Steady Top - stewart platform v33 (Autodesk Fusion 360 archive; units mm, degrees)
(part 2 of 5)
sketch "Sketch19" plane through (-55, -80.325, 20.9) normal (-0.1726, 0.2017, 0.9641) x axis (-0.7598, -0.6502, 0)
  line L1 (-10.1354, 0) -> (10.0189, 0)
  circle C1 centre (0, 0) radius 5
  circle C2 centre (0, 0) radius 3
  circle C3 centre (0, 0) radius 1.5
  point P1 (0, 0)
  point P2 (0, 0)
  point P5 (0, 0)
  coincident P1 P2
  horizontal L1
  coincident P1 P5
  concentric C1 C3
  dimension "d114" diameter C1 = 10
  dimension "d115" diameter C2 = 6
  dimension "d188" diameter C3 = 3
sketch "Sketch23" plane through (0, -80.325, 0) normal (0, -1, 0) x axis (-1, 0, 0)
  circle C1 centre (55, -20.9) radius 8.75
extrude "Extrude22" add sketch "Sketch23" distance 14
copy_paste_bodies "CopyPasteBodies2"
move "Move2"
copy_paste_bodies "CopyPasteBodies3"
move "Move3"
move "Move4"
move "Move5"
revolve "Revolve4" sketch "Sketch19" AlongAngle 360
extrude "Extrude17" new body sketch "Sketch19" profile of L1 C2 along normal blind 20
extrude "Extrude18" new body sketch "Sketch19" profile of L1 C2 blind 10 taper 60 from offset 3
offset_faces "OffsetFaces1" distance -1
combine "Combine5"
sketch "Sketch20" plane through (0, 0, 120.9) normal (0, 0, 1) x axis (-1, 0, 0)
  circle C1 centre (72.8988, 59.4086) radius 2.5224
  circle C2 centre (72.8988, 59.4086) radius 1.625
  circle C3 centre (72.8988, 59.4086) radius 1.55
  concentric C1 C3
  dimension "d122" diameter C3 = 3.1
extrude "Extrude19" cut sketch "Sketch20" profile of C2 C3 against normal blind 6.037
sketch "Sketch21" plane through (0, 0, 123.9) normal (0, 0, 1) x axis (-1, 0, 0)
  circle C1 centre (72.8988, 59.4086) radius 4
  circle C2 centre (72.8988, 59.4086) radius 2.75
  circle C3 centre (72.8988, 59.4086) radius 2.75
extrude "Extrude20" cut sketch "Sketch21" profile of C2 C3 against normal blind 1.037
extrude "Extrude21" add sketch "Sketch13" against normal blind 1.15
offset_faces "OffsetFaces2" distance -0.05
extrude "Extrude23" new body sketch "Sketch10" profile of C1 L1 L2 L3 L8 L9 C2 C3 distance 8
sketch "Sketch24" plane through (0, 0, 124.9) normal (0, 0, 1) x axis (-1, 0, 0)
  line L1 (-64.9519, 82.5) -> (64.9519, 82.5)
  line L2 (-38.9711, -97.5) -> (-103.923, 15)
  line L3 (103.923, 15) -> (38.9711, -97.5)
  arc A1 centre (0, 0) radius 105 clockwise from (64.9519, 82.5) to (103.923, 15)
  arc A2 centre (0, 0) radius 105 clockwise from (-103.923, 15) to (-64.9519, 82.5)
  arc A3 centre (0, 0) radius 105 clockwise from (38.9711, -97.5) to (-38.9711, -97.5)
extrude "Extrude24" add sketch "Sketch19" profile of L1 C3 along normal blind 15
thread "Thread1" ThreadOffset 0 ThreadLength 10
hole "Hole1" HoleDepth 30 HoleDiameter 5.2 TipAngle 118 CBDepth 2 CBDiameter 9.5
circular_pattern "C-Pattern3" TotalAngle 360
canvas "Canvas1"
sketch "Sketch1" plane through (0, 0, 0) normal (1, 0, 0) x axis (0, 1, 0)
  line L1 (-4.2902, -11.5) -> (4.2902, -11.5)
  line L2 (-4.2902, 11.5) -> (-4.2902, -11.5)
  line L3 (4.2902, 11.5) -> (-4.2902, 11.5)
  line L4 (4.2902, -11.5) -> (4.2902, 11.5)
  line L5 (-4.2902, 11.5) -> (4.2902, -11.5)
  line L6 (4.2902, 11.5) -> (-4.2902, -11.5)
  line L7 (-2.75, -5.31) -> (-2.75, 0)
  line L8 (-4.2902, -5.31) -> (-2.75, -5.31)
  line L9 (0, -11.5) -> (0, 0)
  line L10 (-3.2902, -2.75) -> (-4.2902, -2.75)
  line L11 (-3.2902, 4.0144) -> (-3.2902, -2.75)
  line L12 (0, 11.5) -> (0, 0)
  line L13 (0, 7.0012) -> (-0.3033, 7.0012)
  circle C1 centre (0, 0) radius 1.5
  circle C2 centre (0, 0) radius 2.75
  arc A1 centre (-0.3033, 4.0144) radius 2.9868 clockwise from (-3.2902, 4.0144) to (-0.3033, 7.0012)
  point P6 (0, 0)
  point P1 (0, 0)
  point P7 (0, 0)
  point P9 (-2.75, 0)
  point P11 (-4.2902, -5.31)
  point P8 (0, 0)
  point P12 (0, 0)
  point P13 (0, -11.5)
  point P14 (-4.2902, -2.75)
  point P16 (0, 0)
  point P17 (0, 11.5)
  point P18 (0, 7.0012)
  point P2 (4.2902, -11.5)
  point P5 (4.2902, 11.5)
  horizontal L1
  perpendicular L1 L2
  parallel L1 L3
  parallel L2 L4
  coincident L5 P6
  coincident L6 P6
  coincident P1 P6
  coincident P6 P7
  concentric C1 C2
  coincident C2 P9
  tangent C2 L7
  vertical L7
  coincident L2 P11
  perpendicular L2 L8
  coincident P8 P12
  midpoint L1 P13
  coincident L2 P14
  perpendicular L2 L10
  perpendicular L10 L11
  tangent C2 L10
  coincident P8 P16
  midpoint L3 P17
  coincident L12 P18
  perpendicular L12 L13
  tangent L11 A1
  tangent L13 A1
  dimension "d1_1" distance P2 P5 = 23
  dimension "d2_1" diameter C1 = 3
  dimension "d3_1" diameter C2 = 5.5
  dimension "d4_1" distance L2 L11 = 1
  dimension "d5_1" radius A1 = 2.9868
revolve "Revolve1" sketch "Sketch1" AlongAngle 360 named "d6_1"
sketch "Sketch2" plane through (0, 0, 0) normal (1, 0, 0) x axis (0, 1, 0)
  line L1 (-3.2902, 4.0144) -> (-3.2902, -2.75)
  line L2 (0, 7.0012) -> (-0.3033, 7.0012)
  line L3 (0, 11.5) -> (0, 0)
  line L4 (0, 7.0012) -> (0.3033, 7.0012)
  line L5 (3.2902, 4.0144) -> (3.2902, -2.75)
  line L6 (3.2902, -2.75) -> (-3.2902, -2.75)
  arc A1 centre (-0.3033, 4.0144) radius 2.9868 clockwise from (-3.2902, 4.0144) to (-0.3033, 7.0012)
  arc A2 centre (0.3033, 4.0144) radius 2.9868 clockwise from (0.3033, 7.0012) to (3.2902, 4.0144)
  point P2 (-3.2902, -2.75)
  point P13 (3.2902, -2.75)
  point P3 (-3.2902, 4.0144)
  point P11 (3.2902, 4.0144)
  point P4 (-0.3033, 7.0012)
  point P10 (0.3033, 7.0012)
  point P6 (0, 7.0012)
  point P12 (0, 7.0012)
  point P14 (-3.2902, -2.75)
  symmetric P2 L3 P13
  symmetric P3 L3 P11
  symmetric P4 L3 P10
  symmetric A1 L3 A2
  symmetric P6 L3 P12
  coincident P2 P14
extrude "Extrude1" cut sketch "Sketch2" profile of L1 A1 L2 A2 L4 L5 L6 distance 8.05 named "d7_1"
sketch "Sketch3" plane through (0, 0, 0) normal (0, 1, 0) x axis (1, 0, 0)
  line L1 (-2.7532, 2.75) -> (-2.7532, -4.0144)
  line L2 (2.7532, 2.75) -> (-2.7532, 2.75)
  line L3 (2.7532, -4.0144) -> (2.7532, 2.75)
  line L4 (-2.7532, -4.0144) -> (2.7532, -4.0144)
  circle C1 centre (0, 0) radius 2.7532
  circle C2 centre (0, 0) radius 1.5
  point P1 (0, 0)
  point P6 (0, 0)
  point P7 (0, 0)
  coincident P1 P6
  tangent L1 C1
  coincident P1 P7
  dimension "d11_1" diameter C2 = 3
extrude "Extrude2" cut sketch "Sketch3" profile of L1 L2 L3 C1 C2 distance 6.947 named "d9_1"
sketch "Sketch4" plane through (0, 0, 11.5) normal (0, 0, 1) x axis (-1, 0, 0)
  circle C1 centre (0, 0) radius 4.2902
  circle C2 centre (0, 0) radius 2.5
  concentric C1 C2
  dimension "d12_1" diameter C2 = 5
extrude "Extrude3" cut sketch "Sketch4" profile of C2 against normal blind 7.2 named "d13_1"
sketch "Sketch5" plane through (0, 0, 0) normal (0, 1, 0) x axis (1, 0, 0)
  circle C1 centre (0, -9.2817) radius 1.25
  dimension "d15_1" diameter C1 = 2.5
extrude "Extrude4" cut sketch "Sketch5" along normal blind 9.938 named "d16_1"
fillet "Fillet1" radius 0.1 named "d19_1"
fillet "Fillet2" radius 0.1 named "d21_1"
component_from_bodies "Body->Comp1"
base_feature "Base Feature1"
position "Position1"
sketch "Sketch6" plane through (0, 0, 0) normal (1, 0, 0) x axis (0, 1, 0)
  line L1 (-3.25, -3.25) -> (3.25, -3.25)
  line L2 (-3.25, 3.25) -> (-3.25, -3.25)
  line L3 (3.25, 3.25) -> (-3.25, 3.25)
  line L4 (3.25, -3.25) -> (3.25, 3.25)
  line L5 (-3.25, 3.25) -> (3.25, -3.25)
  line L6 (3.25, 3.25) -> (-3.25, -3.25)
  circle C1 centre (0, 0) radius 1.5
  point P7 (0, 0)
  point P2 (0, 0)
  point P3 (3.25, -3.25)
  point P4 (-3.25, -3.25)
  horizontal L1
  perpendicular L1 L2
  parallel L1 L3
  parallel L2 L4
  coincident L5 P7
  coincident L6 P7
  coincident P2 P7
  equal L1 L4
  dimension "d22_1" distance P3 P4 = 6.5
extrude "Extrude5" new body sketch "Sketch6" profile of C1 L1 L2 L3 L4 distance -3.25 named "d23_1"
chamfer "Chamfer1" distance 0.55 named "d25_1"
extrude "Extrude6" add sketch "Sketch6" profile of C1 distance -5 named "d26_1"
sketch "Sketch7" plane through (0, 0, 0) normal (0, 1, 0) x axis (1, 0, 0)
  circle C1 centre (0, 0) radius 1.5
extrude "Extrude7" add sketch "Sketch7" distance 5 named "d28_1"
split "Split1"
split "Split2"
fillet "Fillet3" radius 0.2 named "d31_1"
chamfer "Chamfer1" distance 0.4 named "d34_1"
thread "Thread1" ThreadOffset 0 named "d36_1" ThreadLength 10 named "d37_1"
component_from_bodies "Body->Comp2"
joint "Assemble1" alignAngle 0 alignOffsetX 0 named "d41_1" alignOffsetY 0 named "d42_1" alignOffsetZ 0.04 named "d43_1"
joint "Assemble2" alignAngle -90 named "d44_1" alignOffsetX 0 named "d45_1" alignOffsetY 0 named "d46_1" alignOffsetZ 0.04 named "d47_1"
joint "Assemble3" alignAngle 0 alignOffsetX 0 alignOffsetY 0 alignOffsetZ 0
pipe "Pipe1" SectionSize 5 SectionThickness 1.25
offset_faces "OffsetFaces1" distance 4.152 (= "1.652 mm + 2.5 mm")
shell "Shell1" innerThickness 1
position "Position8"
joint "Assemble4" alignAngle -90 alignOffsetX 0 alignOffsetY 0 alignOffsetZ 0
offset_faces "OffsetFaces2" distance -2.5
offset_faces "OffsetFaces6" distance 1
offset_faces "OffsetFaces7" distance 1
combine "Combine7"
fillet "Fillet2" radius 0.75
fillet "Fillet3" radius 1
move "Move6"
base_feature "Base Feature1"
position "Position9"
position "Position10"
chamfer "Chamfer1" distance 0.4 named "d35_1_1"
thread "Thread2" ThreadOffset 0 named "d38_1_1" ThreadLength 10 named "d39_1_1"
base_feature "Base Feature1"
position "Position11"
position "Position12"
base_feature "Base Feature1"
position "Position13"
chamfer "Chamfer1" distance 0.4 named "d34_1_1"
thread "Thread1" ThreadOffset 0 named "d36_1_1" ThreadLength 10 named "d37_1_1"
position "Position14"
position "Position15"
joint "Assemble5" alignAngle 0 alignOffsetX 0 alignOffsetY 0 alignOffsetZ 0
joint "Assemble6" alignAngle 0 alignOffsetX 0 alignOffsetY 0 alignOffsetZ 0
joint "Assemble7" alignAngle 90 alignOffsetX 0 alignOffsetY 0 alignOffsetZ -0.04
joint "Assemble8" alignAngle 0 alignOffsetX 0 alignOffsetY 0 alignOffsetZ -0.04
position "Position16"
position "Position17"
position "Position18"
base_feature "Base Feature1"
joint "Assemble9" alignAngle 180 alignOffsetX 0 alignOffsetY 0 alignOffsetZ 0
component_from_bodies "Body->Comp1"
component_from_bodies "Body->Comp2"
mirror_component "MirrorComponent1"
derived_instance "DerivedInstance1"
derived_instance "DerivedInstance2"
derived_instance "DerivedInstance3"
derived_instance "DerivedInstance4"
derived_instance "DerivedInstance5"
derived_instance "DerivedInstance6"
derived_instance "DerivedInstance7"
step "00000000-0000-0000-0000-000000000000" TotalAngle 360
component_insert "Component Insert7"
position "Position19"
component_from_bodies "Body->Comp3"
component_from_bodies "Body->Comp4"
component_from_bodies "Body->Comp5"
work_plane "WorkPlane8" AlongDistance 20
sketch "Sketch25" plane through (0, 0, 57.7) normal (0, 0, 1) x axis (1, 0, 0)
  line L1 (-38.8652, 28.1835) -> (-43.8402, 19.5665)
  line L2 (-38.8869, 28.196) -> (-38.8652, 28.1835)
  line L3 (-28.8244, 45.6247) -> (-38.8869, 28.196)
  line L4 (-28.8027, 45.6122) -> (-28.8244, 45.6247)
  line L5 (-18.6803, 63.1448) -> (-28.8027, 45.6122)
  line L6 (28.8027, 45.6122) -> (18.6803, 63.1448)
  line L7 (28.8244, 45.6247) -> (28.8027, 45.6122)
  line L8 (38.8869, 28.196) -> (28.8244, 45.6247)
  line L9 (38.8652, 28.1835) -> (38.8869, 28.196)
  line L10 (43.8402, 19.5665) -> (38.8652, 28.1835)
  line L11 (43.8619, 19.579) -> (43.8402, 19.5665)
  line L12 (53.9244, 2.1503) -> (43.8619, 19.579)
  line L13 (53.9027, 2.1378) -> (53.9244, 2.1503)
  line L14 (64.0252, -15.3948) -> (53.9027, 2.1378)
  line L15 (25.1, -47.75) -> (45.3449, -47.75)
  line L16 (25.1, -47.775) -> (25.1, -47.75)
  line L17 (4.975, -47.775) -> (25.1, -47.775)
  line L18 (4.975, -47.75) -> (4.975, -47.775)
  line L19 (-4.975, -47.75) -> (4.975, -47.75)
  line L20 (-4.975, -47.775) -> (-4.975, -47.75)
  line L21 (-25.1, -47.775) -> (-4.975, -47.775)
  line L22 (-25.1, -47.75) -> (-25.1, -47.775)
  line L23 (-45.3449, -47.75) -> (-25.1, -47.75)
  line L24 (-53.9027, 2.1378) -> (-64.0252, -15.3948)
  line L25 (-53.9244, 2.1503) -> (-53.9027, 2.1378)
  line L26 (-43.8619, 19.579) -> (-53.9244, 2.1503)
  line L27 (-43.8402, 19.5665) -> (-43.8619, 19.579)
  line L28 (-78.9466, -12.9395) -> (-28.2673, 74.8395)
  line L29 (50.6793, -61.9) -> (-50.6793, -61.9)
  line L30 (28.2673, 74.8395) -> (78.9466, -12.9395)
  line L31 (-71.602, -14.2182) -> (-23.4876, 69.1182)
  line L32 (48.1143, -54.9) -> (-48.1143, -54.9)
  line L33 (23.4876, 69.1182) -> (71.602, -14.2182)
  line L34 (-63.1188, -15.5249) -> (-18.1144, 62.4249)
  line L35 (45.0043, -46.9) -> (-45.0043, -46.9)
  line L36 (18.1144, 62.4249) -> (63.1188, -15.5249)
  arc A1 centre (0, 0) radius 65.85 clockwise from (-18.6803, 63.1448) to (18.6803, 63.1448)
  arc A2 centre (0, 0) radius 65.85 clockwise from (64.0252, -15.3948) to (45.3449, -47.75)
  arc A3 centre (0, 0) radius 65.85 clockwise from (-45.3449, -47.75) to (-64.0252, -15.3948)
  arc A4 centre (0, 0) radius 80 clockwise from (-28.2673, 74.8395) to (28.2673, 74.8395)
  arc A5 centre (0, 0) radius 80 clockwise from (-50.6793, -61.9) to (-78.9466, -12.9395)
  arc A6 centre (0, 0) radius 80 clockwise from (78.9466, -12.9395) to (50.6793, -61.9)
  arc A7 centre (0, 0) radius 73 clockwise from (-23.4876, 69.1182) to (23.4876, 69.1182)
  arc A8 centre (0, 0) radius 73 clockwise from (-48.1143, -54.9) to (-71.602, -14.2182)
  arc A9 centre (0, 0) radius 73 clockwise from (71.602, -14.2182) to (48.1143, -54.9)
  arc A10 centre (0, 0) radius 65 clockwise from (-18.1144, 62.4249) to (18.1144, 62.4249)
  arc A11 centre (0, 0) radius 65 clockwise from (-45.0043, -46.9) to (-63.1188, -15.5249)
  arc A12 centre (0, 0) radius 65 clockwise from (63.1188, -15.5249) to (45.0043, -46.9)
  arc A13 centre (0, 0) radius 62 clockwise from (61.1836, -10.0282) to (39.2764, -47.9725)
  arc A14 centre (0, 0) radius 62 clockwise from (-21.9072, 58.0007) to (21.9072, 58.0007)
  arc A15 centre (0, 0) radius 62 clockwise from (-39.2764, -47.9725) to (-61.1836, -10.0282)
  dimension "d194" = -7
  dimension "d195" = -15
  dimension "d196" = -18
  dimension "d198" C-Pattern1-Angle = 360
extrude "Extrude25" new body sketch "Sketch25" profile of L31 A8 L32 A9 L33 A7 A12 L36 A10 L35 L34 A11 A13 A14 A15 along normal blind 3
extrude "Extrude26" add sketch "Sketch25" profile of A12 L36 A10 L35 L34 A11 A13 A14 A15 to an object
chamfer "Chamfer4" distance 8
component_insert "Component Insert8"
component_insert "Component Insert9"
component_insert "Component Insert10"
component_insert "Component Insert11"
combine "Combine1"
offset_faces "OffsetFaces1" distance 1.3
component_from_bodies "Body->Comp6"
component_insert "Component Insert12"
sketch "Sketch26" plane through (0, 0, 132.3423) normal (0, 0, -1) x axis (1, 0, 0)
  line L1 (-38.9711, -97.5) -> (-103.923, 15)
  line L2 (103.923, 15) -> (38.9711, -97.5)
  line L3 (-64.9519, 82.5) -> (64.9519, 82.5)
  line L4 (12.7, 8.89) -> (12.7, -8.89)
  line L5 (-10.16, 11.43) -> (10.16, 11.43)
  line L6 (-12.7, -8.89) -> (-12.7, 8.89)
  line L7 (10.16, -11.43) -> (-10.16, -11.43)
  line L8 (-10.16, 11.93) -> (10.16, 11.93)
  line L9 (-13.2, -8.89) -> (-13.2, 8.89)
  line L10 (10.16, -11.93) -> (-10.16, -11.93)
  line L11 (13.2, 8.89) -> (13.2, -8.89)
  line L12 (15.2, 8.89) -> (15.2, -8.89)
  line L13 (-10.16, 13.93) -> (10.16, 13.93)
  line L14 (-15.2, -8.89) -> (-15.2, 8.89)
  line L15 (10.16, -13.93) -> (-10.16, -13.93)
  circle C1 centre (15, -92.8365) radius 2.6
  circle C2 centre (-15, -92.8365) radius 2.6
  circle C3 centre (72.8988, 59.4086) radius 2.6
  circle C4 centre (87.8988, 33.4279) radius 2.6
  circle C5 centre (-87.8988, 33.4279) radius 2.6
  circle C6 centre (-72.8988, 59.4086) radius 2.6
  arc A1 centre (0, 0) radius 105 clockwise from (-103.923, 15) to (-64.9519, 82.5)
  arc A2 centre (0, 0) radius 105 clockwise from (38.9711, -97.5) to (-38.9711, -97.5)
  arc A3 centre (0, 0) radius 105 clockwise from (64.9519, 82.5) to (103.923, 15)
  circle C7 centre (10.16, 8.89) radius 1.25
  circle C8 centre (10.16, -8.89) radius 1.25
  circle C9 centre (-3.81, -8.89) radius 0.5
  circle C10 centre (1.27, -8.89) radius 0.5
  circle C11 centre (6.35, -8.89) radius 0.5
  circle C12 centre (-3.81, 8.89) radius 0.5
  circle C13 centre (1.27, 8.89) radius 0.5
  circle C14 centre (6.35, 8.89) radius 0.5
  circle C15 centre (-1.206, 6.223) radius 0.2415
  circle C16 centre (-1.143, 5.016) radius 0.2415
  circle C17 centre (0.894, 4) radius 0.2415
  circle C18 centre (11.684, 6.223) radius 0.2415
  circle C19 centre (3.921, 0.163) radius 0.197
  circle C20 centre (-9.252, 0.508) radius 0.2415
  circle C21 centre (-1.143, 1.778) radius 0.2415
  circle C22 centre (3.15, -2.501) radius 0.2415
  circle C23 centre (1.918, 2.286) radius 0.2415
  circle C24 centre (-9.186, -1.355) radius 0.2415
  circle C25 centre (9.449, 0.275) radius 0.2415
  circle C26 centre (5.08, -9.779) radius 0.2415
  circle C27 centre (8.064, -2.54) radius 0.2415
  circle C28 centre (10.096, -6.032) radius 0.2415
  circle C29 centre (-6.35, 6.731) radius 0.2415
  circle C30 centre (-11.43, 0.064) radius 0.2415
  circle C31 centre (-2.667, -5.144) radius 0.2415
  circle C32 centre (-3.238, -3.492) radius 0.2415
  circle C33 centre (-9.144, 1.968) radius 0.2415
  circle C34 centre (-8.064, -4.572) radius 0.2415
  circle C35 centre (9.398, 1.588) radius 0.2415
  circle C36 centre (6.668, 3.874) radius 0.2415
  circle C37 centre (-10.224, -4.572) radius 0.2415
  circle C38 centre (-9.258, -2.476) radius 0.2415
  circle C39 centre (9.309, -4) radius 0.2415
  circle C40 centre (0.444, 1.842) radius 0.197
  circle C41 centre (2.032, 4.382) radius 0.2415
  circle C42 centre (-1.143, 3.569) radius 0.2415
  circle C43 centre (1.397, 5.982) radius 0.2415
  circle C44 centre (-6.16, 2.54) radius 0.2415
  circle C45 centre (3.81, 8.89) radius 0.5
  circle C46 centre (-1.27, 8.89) radius 0.5
  circle C47 centre (-6.35, 8.89) radius 0.5
  circle C48 centre (3.81, -8.89) radius 0.5
  circle C49 centre (-1.27, -8.89) radius 0.5
  circle C50 centre (-6.35, -8.89) radius 0.5
  circle C51 centre (-10.16, -8.89) radius 1.25
  circle C52 centre (-10.16, 8.89) radius 1.25
  arc A4 centre (10.16, -8.89) radius 2.54 clockwise from (12.7, -8.89) to (10.16, -11.43)
  arc A5 centre (10.16, 8.89) radius 2.54 clockwise from (10.16, 11.43) to (12.7, 8.89)
  arc A6 centre (-10.16, 8.89) radius 2.54 clockwise from (-12.7, 8.89) to (-10.16, 11.43)
  arc A7 centre (-10.16, -8.89) radius 2.54 clockwise from (-10.16, -11.43) to (-12.7, -8.89)
  circle C53 centre (10.16, -8.89) radius 2.05
  circle C54 centre (-10.16, -8.89) radius 2.05
  circle C55 centre (-10.16, 8.89) radius 2.05
  circle C56 centre (10.16, 8.89) radius 2.05
  circle C57 centre (10.16, -8.89) radius 0.4
  circle C58 centre (-10.16, -8.89) radius 0.4
  circle C59 centre (-10.16, 8.89) radius 0.4
  circle C60 centre (10.16, 8.89) radius 0.4
  arc A8 centre (-10.16, 8.89) radius 3.04 clockwise from (-13.2, 8.89) to (-10.16, 11.93)
  arc A9 centre (-10.16, -8.89) radius 3.04 clockwise from (-10.16, -11.93) to (-13.2, -8.89)
  arc A10 centre (10.16, -8.89) radius 3.04 clockwise from (13.2, -8.89) to (10.16, -11.93)
  arc A11 centre (10.16, 8.89) radius 3.04 clockwise from (10.16, 11.93) to (13.2, 8.89)
  arc A12 centre (10.16, 8.89) radius 5.04 clockwise from (10.16, 13.93) to (15.2, 8.89)
  arc A13 centre (-10.16, 8.89) radius 5.04 clockwise from (-15.2, 8.89) to (-10.16, 13.93)
  arc A14 centre (-10.16, -8.89) radius 5.04 clockwise from (-10.16, -13.93) to (-15.2, -8.89)
  arc A15 centre (10.16, -8.89) radius 5.04 clockwise from (15.2, -8.89) to (10.16, -13.93)
  concentric C8 C57
  concentric C51 C58
  concentric C52 C59
  concentric C7 C60
  equal C57 C60
  equal C57 C58
  equal C58 C59
  dimension "d205" = 0.8
  dimension "d206" = 0.8
  dimension "d207" = 0.8
  dimension "d208" = 0.8
  dimension "d213" diameter C57 = 0.8
  dimension "d216" = 0.5
  dimension "d217" = 2.5
extrude "Extrude1" add sketch "Sketch26" profile of C7 C8 C51 C52 C53 C54 C55 C56 along normal blind 5
extrude "Extrude2" cut sketch "Sketch26" profile of C57 C58 C59 C60 along normal blind 8.776 and against normal blind 3
extrude "Extrude3" add sketch "Sketch26" profile of A11 A8 A10 A9 L11 L10 L9 L8 L12 A13 A12 A15 L13 A14 L15 L14 along normal blind 6.7
position "Position20"
sketch "Sketch27" plane through (0, 0, 140.3423) normal (0, 0, 1) x axis (-1, 0, 0)
  line L1 (-64.9519, 82.5) -> (64.9519, 82.5)
  line L2 (-38.9711, -97.5) -> (-103.923, 15)
  line L3 (103.923, 15) -> (38.9711, -97.5)
  circle C1 centre (-15, -92.8365) radius 4.75
  circle C2 centre (15, -92.8365) radius 4.75
  circle C3 centre (-72.8988, 59.4086) radius 4.75
  circle C4 centre (-87.8988, 33.4279) radius 4.75
  circle C5 centre (87.8988, 33.4279) radius 4.75
  circle C6 centre (72.8988, 59.4086) radius 4.75
  arc A1 centre (0, 0) radius 105 clockwise from (64.9519, 82.5) to (103.923, 15)
  arc A2 centre (0, 0) radius 105 clockwise from (-103.923, 15) to (-64.9519, 82.5)
  arc A3 centre (0, 0) radius 105 clockwise from (38.9711, -97.5) to (-38.9711, -97.5)
  circle C7 centre (11.1879, -4.7415) radius 1.48
  dimension "d220" diameter C7 = 2.96
extrude "Extrude4" cut sketch "Sketch27" profile of C7 against normal blind 12.262
chamfer "Chamfer1" distance 6.7
chamfer "Chamfer2" distance 1
pipe "Pipe1" SectionSize 5 named "d149_1" SectionThickness 1.25 named "d150_1"
offset_faces "OffsetFaces1" distance 4.152 (= "1.652 mm + 2.5 mm") named "d151_1"
shell "Shell1" innerThickness 1 named "d152_1"
offset_faces "OffsetFaces2" distance -2.5 named "d157_1"
offset_faces "OffsetFaces3" distance -29
component_insert "Component Insert13"
component_insert "Component Insert14"
component_insert "Component Insert15"
joint "Assemble10" alignAngle 180 alignOffsetX 0 alignOffsetY 0 alignOffsetZ 0
joint "Assemble11" alignAngle 180 alignOffsetX 0 alignOffsetY 0 alignOffsetZ 0
copy_paste "CopyPaste2"
copy_paste "CopyPaste3"
copy_paste "CopyPaste4"
copy_paste "CopyPaste5"
work_plane "WorkPlane9" AlongDistance -92.942
sketch "Sketch28" plane through (0, 0, 113.842) normal (0, 0, -1) x axis (-1, 0, 0)
  curve K1 (76.9182, -57.9086) -> (76.9593, -60.7935)
  line L1 (76.1889, -57.9086) -> (76.1889, -60.9086)
  line L2 (69.6086, -60.9086) -> (69.6086, -57.9086)
  curve K2 (68.8794, -57.9086) -> (68.8383, -60.7935)
  line L3 (69.6086, -59.4086) -> (76.1889, -59.4086)
  line L4 (72.7458, -55.9782) -> (72.8988, -59.4086)
  point P10 (76.1889, -59.4086)
  point P11 (69.6086, -59.4086)
  point P12 (72.8988, -59.4086)
  midpoint L1 P10
  midpoint L2 P11
  midpoint L3 P12
sketch "wire frame 2" plane through (0, 0, 20.9) normal (0, 0, -1) x axis (-1, 0, 0)
  line L1 (13.125, -83.925) -> (13.125, -87.325)
  line L2 (16.875, -87.325) -> (16.875, -83.925)
  line L3 (13.125, -81.45) -> (13.125, -83.925)
  line L4 (16.875, -83.925) -> (16.875, -81.45)
  curve K1 (14, -78.5) -> (13.1, -80)
  curve K2 (16.9, -80) -> (16, -78.5)
  line L5 (15, -80.325) -> (55, -80.325)
  line L6 (14, -78.5) -> (16, -78.5)
  line L7 (13.125, -87.325) -> (16.875, -87.325)
  line L8 (15, -78.5) -> (15, -87.325)
  line L9 (72.8988, -59.4086) -> (55, -80.325)
  line L10 (15, -80.325) -> (72.8988, -59.4086)
  line L11 (0, 20) -> (0, 2.5)
  line L12 (-15, -80.325) -> (-55, -80.325)
  circle C1 centre (55, -80.325) radius 5.075
  point P2 (55, -80.325)
  point P15 (55, -80.325)
  point P13 (16, -78.5)
  point P16 (16, -78.5)
  point P12 (14, -78.5)
  point P17 (14, -78.5)
  point P6 (16.875, -87.325)
  point P18 (16.875, -87.325)
  point P3 (13.125, -87.325)
  point P19 (13.125, -87.325)
  point P20 (15, -87.325)
  point P21 (15, -78.5)
  point P22 (15, -80.325)
  point P24 (55, -80.325)
  point P23 (72.8988, -59.4086)
  point P25 (72.8988, -59.4086)
  point P28 (-55, -80.325)
  point P29 (-15, -80.325)
  coincident P2 P15
  perpendicular L4 L5
  coincident P13 P16
  coincident P12 P17
  coincident P6 P18
  coincident P3 P19
  midpoint L7 P20
  midpoint L6 P21
  coincident L8 P22
  coincident P2 P24
  coincident P23 P25
  symmetric P15 L11 P28
  symmetric P22 L11 P29
  dimension "d235" distance P15 P22 = 40
  dimension "d236" distance P24 P25 = 96.9334
  dimension "d237" distance P22 P25 = 111.4808
sketch "Sketch30" plane through (0, 0, 20.9) normal (0, 0, -1) x axis (-1, 0, 0)
  line L1 (15, -80.325) -> (55, -80.325)
  circle C1 centre (0, 0) radius 81.7136
  point P1 (0, 0)
  point P4 (0, 0)
  point P3 (15, -80.325)
  coincident P1 P4
  coincident P3 C1
  dimension "d239" diameter C1 = 163.4271
sketch "Sketch31" plane through (0, 0, 113.842) normal (0, 0, -1) x axis (-1, 0, 0)
  line L1 (72.8988, -59.4086) -> (55, -80.325)
  line L2 (15, -80.325) -> (72.8988, -59.4086)
  line L3 (15, -80.325) -> (55, -80.325)
  circle C1 centre (0, 0) radius 94.0405
  point P1 (0, 0)
  point P6 (0, 0)
  point P3 (72.8988, -59.4086)
  coincident P1 P6
  coincident P3 C1
  dimension "d238" diameter C1 = 188.081
surface_patch "SurfacePatch1" sketch "wire frame 2"
mirror "Mirror1" mirrorStitchTolerance 0.1
sketch "Sketch32" plane through (0, 0, 20.9) normal (0, 0, -1) x axis (-1, 0, 0)
  line L1 (72.8988, -59.4086) -> (55, -80.325)
  line L2 (15, -80.325) -> (72.8988, -59.4086)
  line L3 (55, -80.325) -> (15, -80.325)
  line L4 (-55, -80.325) -> (-72.8988, -59.4086)
  line L5 (-15, -80.325) -> (-55, -80.325)
  line L6 (-72.8988, -59.4086) -> (-15, -80.325)
  line L7 (42.0635, 87.7939) -> (62.0635, 53.1529)
  line L8 (62.0635, 53.1529) -> (15, 92.8365)
  line L9 (15, 92.8365) -> (42.0635, 87.7939)
  line L10 (77.0635, 27.1721) -> (97.0635, -7.4689)
  line L11 (97.0635, -7.4689) -> (87.8988, -33.4279)
  line L12 (87.8988, -33.4279) -> (77.0635, 27.1721)
  line L13 (-97.0635, -7.4689) -> (-77.0635, 27.1721)
  line L14 (-77.0635, 27.1721) -> (-87.8988, -33.4279)
  line L15 (-87.8988, -33.4279) -> (-97.0635, -7.4689)
  line L16 (-62.0635, 53.1529) -> (-42.0635, 87.7939)
  line L17 (-42.0635, 87.7939) -> (-15, 92.8365)
  line L18 (-15, 92.8365) -> (-62.0635, 53.1529)
  point P4 (15, -80.325)
  point P7 (-15, -80.325)
  dimension "d260" distance P4 P7 = 30
  dimension "d243" C-Pattern1-Angle = 360
sketch "Sketch33" plane through (0, 0, 20.9) normal (0, 0, -1) x axis (-1, 0, 0)
  line L1 (55, -80.325) -> (15, -80.325)
  line L2 (-15, -80.325) -> (-55, -80.325)
  line L3 (-97.0635, -7.4689) -> (-77.0635, 27.1721)
  line L4 (-62.0635, 53.1529) -> (-42.0635, 87.7939)
  line L5 (42.0635, 87.7939) -> (62.0635, 53.1529)
  line L6 (77.0635, 27.1721) -> (97.0635, -7.4689)
  line L7 (-62.0635, 53.1529) -> (0, 0)
  line L8 (-77.0635, 27.1721) -> (0, 0)
  line L9 (-15, -80.325) -> (0, 0)
  line L10 (15, -80.325) -> (0, 0)
  line L11 (77.0635, 27.1721) -> (0, 0)
  line L12 (62.0635, 53.1529) -> (0, 0)
  line L13 (0, 20) -> (0, 2.5)
  curve K1
  curve K2
  curve K3
  curve K4
  curve K5
  curve K6
  curve K7
  curve K8
  line L14 (72.8988, -59.4086) -> (55, -80.325)
  line L15 (0, -80.325) -> (0, 0)
  line L16 (-15, -80.325) -> (15, -80.325)
  line L17 (-15, -45.6113) -> (-15, -80.325)
  line L18 (15, -46.194) -> (15, -80.325)
  circle C1 centre (0, 0) radius 81.7136
  point P1 (0, 0)
  point P14 (0, 0)
  point P15 (-62.0635, 53.1529)
  point P16 (0, 0)
  point P17 (-62.0635, 53.1529)
  point P18 (0, 0)
  point P6 (-77.0635, 27.1721)
  point P19 (-77.0635, 27.1721)
  point P20 (0, 0)
  point P5 (-15, -80.325)
  point P21 (-15, -80.325)
  point P22 (0, 0)
  point P2 (15, -80.325)
  point P23 (15, -80.325)
  point P24 (0, 0)
  point P13 (77.0635, 27.1721)
  point P25 (77.0635, 27.1721)
  point P26 (0, 0)
  point P10 (62.0635, 53.1529)
  point P27 (62.0635, 53.1529)
  point P32 (15, -80.325)
  point P33 (-15, -80.325)
  point P35 (15, -80.325)
  point P3 (55, -80.325)
  point P30 (72.8988, -59.4086)
  coincident P1 P14
  coincident C1 P15
  coincident P14 P16
  coincident P15 P17
  coincident P14 P18
  coincident P6 P19
  coincident P1 P20
  coincident P5 P21
  coincident P14 P22
  coincident P2 P23
  coincident P1 P24
  coincident P13 P25
  coincident P14 P26
  coincident P10 P27
  perpendicular L2 L15
  coincident P2 P32
  coincident P5 P33
  perpendicular L2 L17
  coincident P2 P35
  perpendicular L16 L18
  vertical L18
  vertical L17
  dimension "d249" angle L9 L10 = 21.155
  dimension "d252" distance P2 P3 = 40
  dimension "d253" angle L8 L10 = 120
  dimension "d259" distance P3 P30 = 96.9334
  dimension "d348" angle L10 L15 = 10.578
  dimension "d349" angle L9 L15 = 10.578
  dimension "d350" angle L8 L15 = 109.422
  dimension "d351" angle L7 L15 = 130.578
  dimension "d352" angle L12 L15 = 49.422
  dimension "d353" angle L11 L15 = 70.578
  dimension "d254" Text1-Height = 10
  dimension "d255" Text2-Height = 10
sketch "Sketch34" plane through (0, 0, 113.842) normal (0, 0, -1) x axis (-1, 0, 0)
  line L1 (0, 0) -> (72.8988, -59.4086)
  line L2 (-72.8988, -59.4086) -> (0, 0)
  circle C1 centre (0, 0) radius 94.0405
  point P1 (0, 0)
  point P8 (0, 0)
  point P2 (72.8988, -59.4086)
  point P9 (72.8988, -59.4086)
  point P10 (0, 0)
  point P3 (-72.8988, -59.4086)
  point P11 (-72.8988, -59.4086)
  coincident P1 P8
  coincident P2 C1
  coincident P2 P9
  coincident P1 P10
  coincident P3 P11
  dimension "d256" diameter C1 = 188.081
  dimension "d258" angle L1 L2 = 101.644
component_insert "Component Insert16"
component_insert "Component Insert17"
component_insert "Component Insert18"
work_plane "WorkPlane10" AlongDistance 0
position "Position21"
sketch "Sketch35" plane through (0, 0, 63.038) normal (0, 0, -1) x axis (-1, 0, 0)
  line L1 (34.0436, -12.6037) -> (11.6436, -12.6037)
  line L2 (10.0436, -11.0037) -> (10.0436, -7.2037)
  line L3 (11.6436, -5.6037) -> (31.0436, -5.6037)
  line L4 (34.0436, -2.6037) -> (34.0436, 16.3963)
  line L5 (31.0436, 19.3963) -> (13.6436, 19.3963)
  line L6 (12.0436, 20.9963) -> (12.0436, 34.3963)
  line L7 (9.0436, 37.3963) -> (-19.9564, 37.3963)
  line L8 (-22.9564, 34.3963) -> (-22.9564, -44.6037)
  line L9 (-19.9564, -47.6037) -> (34.0436, -47.6037)
  line L10 (37.0436, -44.6037) -> (37.0436, -15.6037)
  line L11 (-23.4876, 69.1182) -> (-71.602, -14.2182)
  line L12 (71.602, -14.2182) -> (23.4876, 69.1182)
  line L13 (-48.1143, -54.9) -> (48.1143, -54.9)
  line L14 (58.8354, -16.1059) -> (15.4696, 59.0059)
  line L15 (-43.3658, -42.9) -> (43.3658, -42.9)
  line L16 (-15.4696, 59.0059) -> (-58.8354, -16.1059)
  line L17 (-23.4876, 43) -> (23.4876, 43)
  line L18 (-23.4876, 103) -> (-23.4876, 43)
  line L19 (23.4876, 103) -> (-23.4876, 103)
  line L20 (23.4876, 43) -> (23.4876, 103)
  line L21 (-23.4876, 103) -> (23.4876, 43)
  line L22 (23.4876, 103) -> (-23.4876, 43)
  line L23 (-77.4568, -71.8409) -> (-25.4953, -41.8409)
  line L24 (-100.9444, -31.1591) -> (-77.4568, -71.8409)
  line L25 (-48.9829, -1.1591) -> (-100.9444, -31.1591)
  line L26 (-25.4953, -41.8409) -> (-48.9829, -1.1591)
  line L27 (100.9444, -31.1591) -> (48.9829, -1.1591)
  line L28 (77.4568, -71.8409) -> (100.9444, -31.1591)
  line L29 (25.4953, -41.8409) -> (77.4568, -71.8409)
  line L30 (48.9829, -1.1591) -> (25.4953, -41.8409)
  line L31 (-19.9564, -50.1037) -> (34.0436, -50.1037)
  line L32 (-25.4564, 34.3963) -> (-25.4564, -44.6037)
  line L33 (9.0436, 39.8963) -> (-19.9564, 39.8963)
  line L34 (14.5436, 21.8963) -> (14.5436, 34.3963)
  line L35 (31.0436, 21.8963) -> (14.5436, 21.8963)
  line L36 (36.5436, -2.6037) -> (36.5436, 16.3963)
  line L37 (12.5436, -8.1037) -> (31.0436, -8.1037)
  line L38 (12.5436, -10.1037) -> (12.5436, -8.1037)
  line L39 (34.0436, -10.1037) -> (12.5436, -10.1037)
  line L40 (39.5436, -44.6037) -> (39.5436, -15.6037)
  circle C1 centre (34.4286, -23.4298) radius 0.5334
  circle C2 centre (-14.9564, -5.1037) radius 0.45
  circle C3 centre (29.3486, -38.6698) radius 0.5334
  circle C4 centre (22.9186, 15.7713) radius 0.5
  circle C5 centre (21.7286, -23.4298) radius 0.5334
  circle C6 centre (28.9186, 13.2613) radius 0.52
  circle C7 centre (26.8086, -38.6698) radius 0.5334
  circle C8 centre (28.9186, 15.8013) radius 0.52
  circle C9 centre (29.3486, -23.4298) radius 0.5334
  circle C10 centre (28.9186, 5.6413) radius 0.52
  circle C11 centre (21.7286, -38.6698) radius 0.5334
  circle C12 centre (28.9186, 3.1013) radius 0.52
  circle C13 centre (24.2686, -23.4298) radius 0.5334
  circle C14 centre (28.9186, 8.1813) radius 0.52
  circle C15 centre (24.2686, -38.6698) radius 0.5334
  circle C16 centre (28.9186, 10.7213) radius 0.52
  circle C17 centre (31.8886, -23.4298) radius 0.5334
  circle C18 centre (31.9186, -43.2287) radius 0.45
  circle C19 centre (34.4286, -38.6698) radius 0.5334
  circle C20 centre (-17.4564, -22.1037) radius 0.45
  circle C21 centre (19.1886, -23.4298) radius 0.5334
  circle C22 centre (-0.4564, -15.1037) radius 0.45
  circle C23 centre (31.8886, -38.6698) radius 0.5334
  circle C24 centre (-14.4564, -38.7625) radius 0.45
  circle C25 centre (26.8086, -23.4298) radius 0.5334
  circle C26 centre (3.0872, 15.5174) radius 0.45
  circle C27 centre (28.9186, -1.9787) radius 0.52
  circle C28 centre (6.6686, -44.4171) radius 0.45
  circle C29 centre (19.1886, -38.6698) radius 0.5334
  circle C30 centre (28.9186, 0.5613) radius 0.52
  arc A1 centre (11.6436, -11.0037) radius 1.6 clockwise from (11.6436, -12.6037) to (10.0436, -11.0037)
  arc A2 centre (11.6436, -7.2037) radius 1.6 clockwise from (10.0436, -7.2037) to (11.6436, -5.6037)
  arc A3 centre (31.0436, -2.6037) radius 3 clockwise from (34.0436, -2.6037) to (31.0436, -5.6037)
  arc A4 centre (31.0436, 16.3963) radius 3 clockwise from (31.0436, 19.3963) to (34.0436, 16.3963)
  arc A5 centre (13.6436, 20.9963) radius 1.6 clockwise from (13.6436, 19.3963) to (12.0436, 20.9963)
  arc A6 centre (9.0436, 34.3963) radius 3 clockwise from (9.0436, 37.3963) to (12.0436, 34.3963)
  arc A7 centre (-19.9564, 34.3963) radius 3 clockwise from (-22.9564, 34.3963) to (-19.9564, 37.3963)
  arc A8 centre (-19.9564, -44.6037) radius 3 clockwise from (-19.9564, -47.6037) to (-22.9564, -44.6037)
  arc A9 centre (34.0436, -44.6037) radius 3 clockwise from (37.0436, -44.6037) to (34.0436, -47.6037)
  arc A10 centre (34.0436, -15.6037) radius 3 clockwise from (34.0436, -12.6037) to (37.0436, -15.6037)
  arc A11 centre (0, 0) radius 73 clockwise from (-23.4876, 69.1182) to (23.4876, 69.1182)
  arc A12 centre (0, 0) radius 73 clockwise from (71.602, -14.2182) to (48.1143, -54.9)
  arc A13 centre (0, 0) radius 73 clockwise from (-48.1143, -54.9) to (-71.602, -14.2182)
  arc A14 centre (0, 0) radius 61 clockwise from (60.8394, 4.423) to (26.5893, -54.9)
  arc A15 centre (0, 0) radius 61 clockwise from (-26.5893, -54.9) to (-60.8394, 4.423)
  arc A16 centre (0, 0) radius 61 clockwise from (-34.2502, 50.477) to (34.0436, 50.6165)
  arc A17 centre (-19.9564, -44.6037) radius 5.5 clockwise from (-19.9564, -50.1037) to (-25.4564, -44.6037)
  arc A18 centre (-19.9564, 34.3963) radius 5.5 clockwise from (-25.4564, 34.3963) to (-19.9564, 39.8963)
  arc A19 centre (9.0436, 34.3963) radius 5.5 clockwise from (9.0436, 39.8963) to (14.5436, 34.3963)
  arc A20 centre (31.0436, 16.3963) radius 5.5 clockwise from (31.0436, 21.8963) to (36.5436, 16.3963)
  arc A21 centre (31.0436, -2.6037) radius 5.5 clockwise from (36.5436, -2.6037) to (31.0436, -8.1037)
  arc A22 centre (34.0436, -15.6037) radius 5.5 clockwise from (34.0436, -10.1037) to (39.5436, -15.6037)
  arc A23 centre (34.0436, -44.6037) radius 5.5 clockwise from (39.5436, -44.6037) to (34.0436, -50.1037)
  point P72 (43.3658, -42.9)
  point P70 (58.8354, -16.1059)
  point P73 (-43.3658, -42.9)
  point P75 (-58.8354, -16.1059)
  point P76 (-15.4696, 59.0059)
  point P69 (15.4696, 59.0059)
  point P79 (-34.2502, 50.477)
  point P80 (-60.8394, 4.423)
  point P81 (-26.5893, -54.9)
  point P82 (26.5893, -54.9)
  point P83 (60.8394, 4.423)
  point P88 (0, 73)
  point P64 (23.4876, 69.1182)
  point P84 (23.4876, 43)
  point P87 (23.4876, 103)
  concentric A12 A14
  concentric A13 A15
  concentric A11 A16
  coincident P72 A14
  coincident P70 A14
  coincident P73 A15
  coincident P75 A15
  coincident P76 A16
  coincident P69 A16
  coincident L11 P79
  coincident L11 P80
  coincident L13 P81
  coincident L13 P82
  coincident L12 P83
  horizontal L17
  perpendicular L17 L18
  parallel L17 L19
  parallel L18 L20
  coincident L21 P88
  coincident L22 P88
  midpoint A11 P88
  coincident P64 L20
  dimension "d263" distance P84 P87 = 60
  dimension "d266" = 2.5
  dimension "d265" C-Pattern1-Angle = 360
extrude "Extrude27" new body sketch "Sketch35" profile of A16 A15 L15 L16 L14 A14 L18 L20 L23 L25 L27 L29 along normal blind 2.5
sketch "Sketch36" plane through (0, 0, 63.038) normal (0, 0, -1) x axis (-1, 0, 0)
  line L1 (-19.9564, -47.6037) -> (34.0436, -47.6037)
  line L2 (-22.9564, 34.3963) -> (-22.9564, -44.6037)
  line L3 (9.0436, 37.3963) -> (-19.9564, 37.3963)
  line L4 (12.0436, 20.9963) -> (12.0436, 34.3963)
  line L5 (31.0436, 19.3963) -> (13.6436, 19.3963)
  line L6 (34.0436, -2.6037) -> (34.0436, 16.3963)
  line L7 (11.6436, -5.6037) -> (31.0436, -5.6037)
  line L8 (10.0436, -11.0037) -> (10.0436, -7.2037)
  line L9 (34.0436, -12.6037) -> (11.6436, -12.6037)
  line L10 (37.0436, -44.6037) -> (37.0436, -15.6037)
  line L11 (-19.9564, -50.1037) -> (34.0436, -50.1037)
  line L12 (-25.4564, 34.3963) -> (-25.4564, -44.6037)
  line L13 (9.0436, 39.8963) -> (-19.9564, 39.8963)
  line L14 (14.5436, 21.8963) -> (14.5436, 34.3963)
  line L15 (31.0436, 21.8963) -> (14.5436, 21.8963)
  line L16 (36.5436, -2.6037) -> (36.5436, 16.3963)
  line L17 (12.5436, -8.1037) -> (31.0436, -8.1037)
  line L18 (12.5436, -10.1037) -> (12.5436, -8.1037)
  line L19 (34.0436, -10.1037) -> (12.5436, -10.1037)
  line L20 (39.5436, -44.6037) -> (39.5436, -15.6037)
  line L21 (36.0436, -44.6037) -> (36.0436, -15.6037)
  line L22 (34.0436, -13.6037) -> (11.6436, -13.6037)
  line L23 (9.0436, -11.0037) -> (9.0436, -7.2037)
  line L24 (11.6436, -4.6037) -> (31.0436, -4.6037)
  line L25 (33.0436, -2.6037) -> (33.0436, 16.3963)
  line L26 (31.0436, 18.3963) -> (13.6436, 18.3963)
  line L27 (11.0436, 20.9963) -> (11.0436, 34.3963)
  line L28 (9.0436, 36.3963) -> (-19.9564, 36.3963)
  line L29 (-21.9564, 34.3963) -> (-21.9564, -44.6037)
  line L30 (-19.9564, -46.6037) -> (34.0436, -46.6037)
  line L31 (38.9325, -44.6037) -> (38.9325, -15.6037)
  line L32 (-34.0436, -49.4926) -> (34.0436, -49.4926)
  line L33 (-24.8452, 34.3963) -> (-24.8452, -44.6037)
  line L34 (9.0436, 39.2852) -> (-19.9564, 39.2852)
  line L35 (13.9325, 21.2852) -> (13.9325, 34.3963)
  line L36 (31.0436, 21.2852) -> (13.9325, 21.2852)
  line L37 (35.9325, -2.6037) -> (35.9325, 16.3963)
  line L38 (11.9325, -7.4926) -> (31.0436, -7.4926)
  line L39 (11.9325, -10.7148) -> (11.9325, -7.4926)
  line L40 (34.0436, -10.7148) -> (11.9325, -10.7148)
  line L41 (0, -75.7937) -> (0, 0)
  line L42 (-24.8452, -36.3956) -> (-38.9325, -44.6037)
  line L43 (-28.0468, -44.6037) -> (-19.9564, -44.6037)
  line L44 (-28.0468, -52.4264) -> (-28.0468, -44.6037)
  line L45 (-19.9564, -52.4264) -> (-28.0468, -52.4264)
  line L46 (-19.9564, -44.6037) -> (-19.9564, -52.4264)
  line L47 (42.0931, -44.6037) -> (34.0436, -44.6037)
  line L48 (42.0931, -52.7689) -> (42.0931, -44.6037)
  line L49 (34.0436, -52.7689) -> (42.0931, -52.7689)
  line L50 (34.0436, -44.6037) -> (34.0436, -52.7689)
  line L51 (42.0931, -15.6037) -> (34.0436, -15.6037)
  line L52 (42.0931, -9.0313) -> (42.0931, -15.6037)
  line L53 (34.0436, -9.0313) -> (42.0931, -9.0313)
  line L54 (34.0436, -15.6037) -> (34.0436, -9.0313)
  line L55 (38.0684, -2.6037) -> (31.0436, -2.6037)
  line L56 (38.0684, -9.0313) -> (38.0684, -2.6037)
  line L57 (31.0436, -9.0313) -> (38.0684, -9.0313)
  line L58 (31.0436, -2.6037) -> (31.0436, -9.0313)
  line L59 (38.0684, 16.3963) -> (31.0436, 16.3963)
  line L60 (38.0684, 23.4431) -> (38.0684, 16.3963)
  line L61 (31.0436, 23.4431) -> (38.0684, 23.4431)
  line L62 (31.0436, 16.3963) -> (31.0436, 23.4431)
  line L63 (16.4916, 34.3963) -> (9.0436, 34.3963)
  line L64 (16.4916, 41.6027) -> (16.4916, 34.3963)
  line L65 (9.0436, 41.6027) -> (16.4916, 41.6027)
  line L66 (9.0436, 34.3963) -> (9.0436, 41.6027)
  line L67 (-26.0166, 34.3963) -> (-19.9564, 34.3963)
  line L68 (-26.0166, 40.5491) -> (-26.0166, 34.3963)
  line L69 (-19.9564, 40.5491) -> (-26.0166, 40.5491)
  line L70 (-19.9564, 34.3963) -> (-19.9564, 40.5491)
  arc A1 centre (34.0436, -44.6037) radius 3 clockwise from (37.0436, -44.6037) to (34.0436, -47.6037)
  arc A2 centre (-19.9564, -44.6037) radius 3 clockwise from (-19.9564, -47.6037) to (-22.9564, -44.6037)
  arc A3 centre (-19.9564, 34.3963) radius 3 clockwise from (-22.9564, 34.3963) to (-19.9564, 37.3963)
  arc A4 centre (9.0436, 34.3963) radius 3 clockwise from (9.0436, 37.3963) to (12.0436, 34.3963)
  arc A5 centre (13.6436, 20.9963) radius 1.6 clockwise from (13.6436, 19.3963) to (12.0436, 20.9963)
  arc A6 centre (31.0436, 16.3963) radius 3 clockwise from (31.0436, 19.3963) to (34.0436, 16.3963)
  arc A7 centre (31.0436, -2.6037) radius 3 clockwise from (34.0436, -2.6037) to (31.0436, -5.6037)
  arc A8 centre (11.6436, -7.2037) radius 1.6 clockwise from (10.0436, -7.2037) to (11.6436, -5.6037)
  arc A9 centre (11.6436, -11.0037) radius 1.6 clockwise from (11.6436, -12.6037) to (10.0436, -11.0037)
  arc A10 centre (34.0436, -15.6037) radius 3 clockwise from (34.0436, -12.6037) to (37.0436, -15.6037)
  arc A11 centre (34.0436, -44.6037) radius 5.5 clockwise from (39.5436, -44.6037) to (34.0436, -50.1037)
  arc A12 centre (-19.9564, -44.6037) radius 5.5 clockwise from (-19.9564, -50.1037) to (-25.4564, -44.6037)
  arc A13 centre (-19.9564, 34.3963) radius 5.5 clockwise from (-25.4564, 34.3963) to (-19.9564, 39.8963)
  arc A14 centre (9.0436, 34.3963) radius 5.5 clockwise from (9.0436, 39.8963) to (14.5436, 34.3963)
  arc A15 centre (31.0436, 16.3963) radius 5.5 clockwise from (31.0436, 21.8963) to (36.5436, 16.3963)
  arc A16 centre (31.0436, -2.6037) radius 5.5 clockwise from (36.5436, -2.6037) to (31.0436, -8.1037)
  arc A17 centre (34.0436, -15.6037) radius 5.5 clockwise from (34.0436, -10.1037) to (39.5436, -15.6037)
  arc A18 centre (34.0436, -44.6037) radius 2 clockwise from (36.0436, -44.6037) to (34.0436, -46.6037)
  arc A19 centre (34.0436, -15.6037) radius 2 clockwise from (34.0436, -13.6037) to (36.0436, -15.6037)
  arc A20 centre (11.6436, -11.0037) radius 2.6 clockwise from (11.6436, -13.6037) to (9.0436, -11.0037)
  arc A21 centre (11.6436, -7.2037) radius 2.6 clockwise from (9.0436, -7.2037) to (11.6436, -4.6037)
  arc A22 centre (31.0436, -2.6037) radius 2 clockwise from (33.0436, -2.6037) to (31.0436, -4.6037)
  arc A23 centre (31.0436, 16.3963) radius 2 clockwise from (31.0436, 18.3963) to (33.0436, 16.3963)
  arc A24 centre (13.6436, 20.9963) radius 2.6 clockwise from (13.6436, 18.3963) to (11.0436, 20.9963)
  arc A25 centre (9.0436, 34.3963) radius 2 clockwise from (9.0436, 36.3963) to (11.0436, 34.3963)
  arc A26 centre (-19.9564, 34.3963) radius 2 clockwise from (-21.9564, 34.3963) to (-19.9564, 36.3963)
  arc A27 centre (-19.9564, -44.6037) radius 2 clockwise from (-19.9564, -46.6037) to (-21.9564, -44.6037)
  arc A28 centre (34.0436, -44.6037) radius 4.8889 clockwise from (38.9325, -44.6037) to (34.0436, -49.4926)
  arc A29 centre (-19.9564, -44.6037) radius 4.8889 clockwise from (-19.9564, -49.4926) to (-24.8452, -44.6037)
  arc A30 centre (-19.9564, 34.3963) radius 4.8889 clockwise from (-24.8452, 34.3963) to (-19.9564, 39.2852)
  arc A31 centre (9.0436, 34.3963) radius 4.8889 clockwise from (9.0436, 39.2852) to (13.9325, 34.3963)
  arc A32 centre (31.0436, 16.3963) radius 4.8889 clockwise from (31.0436, 21.2852) to (35.9325, 16.3963)
  arc A33 centre (31.0436, -2.6037) radius 4.8889 clockwise from (35.9325, -2.6037) to (31.0436, -7.4926)
  arc A34 centre (34.0436, -15.6037) radius 4.8889 clockwise from (34.0436, -10.7148) to (38.9325, -15.6037)
  arc A35 centre (-34.0436, -44.6037) radius 4.8889 clockwise from (-34.0436, -49.4926) to (-38.9325, -44.6037)
  point P1 (0, 0)
  point P110 (0, 0)
  point P87 (38.9325, -44.6037)
  point P114 (-38.9325, -44.6037)
  point P89 (34.0436, -49.4926)
  point P113 (-34.0436, -49.4926)
  point P90 (-19.9564, -49.4926)
  point P115 (-24.8452, -36.3956)
  point P91 (-19.9564, -44.6037)
  point P116 (-19.9564, -44.6037)
  point P88 (34.0436, -44.6037)
  point P120 (34.0436, -44.6037)
  point P31 (34.0436, -15.6037)
  point P124 (34.0436, -15.6037)
  point P130 (38.0684, -9.0313)
  point P104 (31.0436, -2.6037)
  point P128 (31.0436, -2.6037)
  point P101 (31.0436, 16.3963)
  point P132 (31.0436, 16.3963)
  point P43 (9.0436, 34.3963)
  point P136 (9.0436, 34.3963)
  point P40 (-19.9564, 34.3963)
  point P140 (-19.9564, 34.3963)
  coincident P1 P110
  parallel L29 L41
  symmetric P87 L41 P114
  symmetric P89 L41 P113
  symmetric A28 L41 A35
  concentric A1 A28
  concentric A2 A29
  concentric A3 A30
  concentric A4 A31
  concentric A6 A32
  concentric A7 A33
  concentric A10 A34
  tangent L40 A34
  tangent A33 L38
  tangent A32 L37
  tangent L36 A32
  tangent L37 A33
  tangent L34 A31
  tangent A30 L34
  tangent A28 L32
  tangent A29 L33
  tangent A31 L35
  tangent L33 A30
  tangent L32 A29
  tangent L31 A28
  tangent L31 A34
  coincident P90 L32
  coincident L33 P115
  horizontal L43
  vertical L44
  horizontal L45
  vertical L46
  coincident P91 P116
  horizontal L47
  vertical L48
  horizontal L49
  vertical L50
  coincident P88 P120
  horizontal L51
  vertical L52
  horizontal L53
  vertical L54
  coincident P31 P124
  horizontal L55
  vertical L56
  horizontal L57
  vertical L58
  midpoint L53 P130
  coincident P104 P128
  horizontal L59
  vertical L60
  horizontal L61
  vertical L62
  coincident P101 P132
  horizontal L63
  vertical L64
  horizontal L65
  vertical L66
  coincident P43 P136
  horizontal L67
  vertical L68
  horizontal L69
  vertical L70
  coincident P40 P140
  dimension "d269" = 1
extrude "Extrude28" add sketch "Sketch36" profile of A1 L1 A2 L2 A3 L3 A4 L4 A5 L5 A6 L6 A7 L7 A8 L8 A9 L9 A10 L10 A12 L12 A18 A20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 along normal blind 2.5
extrude "Extrude29" cut sketch "Sketch36" profile of A18 A20 L25 A26 L27 A21 A19 A27 L24 A23 L28 L21 L29 L30 A22 L22 A25 A24 L23 L26 to an object
extrude "Extrude30" add sketch "Sketch36" profile of A1 A2 A3 A4 A6 A7 A10 A11 A12 A13 A14 A15 A16 A17 A28 A29 A34 A33 A32 A31 L32 A30 L43 L46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 against normal blind 2.5
loft "Loft1"
loft "Loft2"
loft "Loft3"
step "SurfaceOffset1" offset 0
step "SurfaceOffset2" offset 0
step "SurfaceOffset3" offset 0
surface_delete_face "SurfaceDeleteFace1"
surface_stitch "SurfaceStitch1" StitchingTolerence 0.1
thicken "Thicken1" Thickness -3
surface_stitch "SurfaceStitch2" StitchingTolerence 0.1
thicken "Thicken2" Thickness -3
surface_stitch "SurfaceStitch3" StitchingTolerence 0.1
thicken "Thicken3" Thickness -3
combine "Combine8"
fillet "Fillet4" radius 2
fillet "Fillet5" radius 3.016
fillet "Fillet6" radius 68.204
fillet "Fillet7" radius 405.4855
fillet "Fillet8" radius 8
pipe "Pipe1" SectionSize 1 SectionThickness 0.25
fillet "Fillet9" radius 1.1
pipe "Pipe2" SectionSize 1 SectionThickness 0.25
pipe "Pipe3" SectionSize 1 SectionThickness 0.25
pipe "Pipe4" SectionSize 1 SectionThickness 0.25
pipe "Pipe5" SectionSize 1 SectionThickness 0.25
sketch "Sketch37" plane through (0, 0, 0) normal (0, 1, 0) x axis (1, 0, 0)
  line L1 (7.5, -53.5) -> (-7.5, -53.5)
  line L2 (7.5, -46.5) -> (7.5, -53.5)
  line L3 (-7.5, -46.5) -> (7.5, -46.5)
  line L4 (-7.5, -53.5) -> (-7.5, -46.5)
  line L5 (7.5, -46.5) -> (-7.5, -53.5)
  line L6 (-7.5, -46.5) -> (7.5, -53.5)
  line L7 (0, -50) -> (0, 0)
  point P6 (0, -50)
  point P1 (0, 0)
  point P7 (0, 0)
  point P8 (0, -50)
  point P2 (-7.5, -53.5)
  point P3 (7.5, -53.5)
  point P4 (7.5, -46.5)
  horizontal L1
  perpendicular L1 L2
  parallel L1 L3
  parallel L2 L4
  coincident L5 P6
  coincident L6 P6
  coincident P1 P7
  coincident P6 P8
  vertical L7
  dimension "d320" distance P2 P3 = 15
  dimension "d321" distance P3 P4 = 7
  dimension "d322" distance P7 P8 = 50
extrude "Extrude31" cut sketch "Sketch37" profile of L1 L2 L3 L4 along normal blind 82.308
work_plane "WorkPlane11" AlongDistance 0
sketch "Sketch38" plane through (-38.6186, 0, 0) normal (-1, 0, 0) x axis (0, -1, 0)
  line L1 (28.1548, 52.688) -> (33.9448, 52.688)
  line L2 (33.9448, 49.478) -> (28.1548, 49.478)
  line L3 (28.1548, 49.778) -> (33.9448, 49.778)
  line L4 (33.9448, 52.388) -> (28.1548, 52.388)
  line L5 (28.1548, 55.688) -> (33.9448, 55.688)
  line L6 (33.9448, 46.478) -> (28.1548, 46.478)
  arc A1 centre (33.9448, 51.083) radius 1.605 clockwise from (33.9448, 52.688) to (33.9448, 49.478)
  arc A2 centre (28.1548, 51.083) radius 1.605 clockwise from (28.1548, 49.478) to (28.1548, 52.688)
  arc A3 centre (28.1548, 51.083) radius 1.305 clockwise from (28.1548, 49.778) to (28.1548, 52.388)
  arc A4 centre (33.9448, 51.083) radius 1.305 clockwise from (33.9448, 52.388) to (33.9448, 49.778)
  arc A5 centre (33.9448, 51.083) radius 4.605 clockwise from (33.9448, 55.688) to (33.9448, 46.478)
  arc A6 centre (28.1548, 51.083) radius 4.605 clockwise from (28.1548, 46.478) to (28.1548, 55.688)
  dimension "d324" = 3
extrude "Extrude32" cut sketch "Sketch38" along normal blind 26.479
offset_faces "OffsetFaces8" distance -1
